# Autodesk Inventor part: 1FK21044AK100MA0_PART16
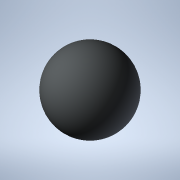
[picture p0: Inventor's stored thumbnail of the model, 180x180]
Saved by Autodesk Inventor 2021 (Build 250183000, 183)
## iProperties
Created: 2025-04
Part Number: 1FK21044AK100MA0_PART16
Material: Generic
Catalog Web Link: www.3dfindit.com
Description: -Servo synchronous motor
Document SubType Name: Modeling
Designer: psAdmin
Mass: 0.137258 g
Surface Area: 1.2868 cm^2
Volume: 0.137258 cm^3
Density: 1 g/cm^3
Appearance: PSOLRGB-212-217-219
Category: PARTsolutions
Title: 1FK21044AK100MA0_PART16
Author: Cadenas PARTsolutions
Comments: Servo synchronous motor
Sending System: PARTsolutions
Preprocessor: ST-DEVELOPER v19.3
PSOL_IDENT_0: {$CADENAS_DATA/23d-libs/siemens_ag/_cat_/5e/d8/1fk21044ak100ma0.prj},216 {VTYP=3D},{NB=1FK21044AK100
PSOL_IDENT_1: MA0_PART16},{LINA=1FK21044AK100MA0_PART16},{NN=1FK21044AK100MA0_PART16},{NOPRJ=TRUE},{DATE=19.08.202
PSOL_IDENT_2: 5 14:00:41},{GEOMDATE=30.07.2025 02:00:53},{VERSION=},{LINEID=10},{WBVAR=},{WBNUMERIC=}  {NB=1FK2104
PSOL_IDENT_3: 4AK100MA0_PART16},{LINA=1FK21044AK100MA0_PART16},{KT=DUMMY},{PREVIEW=../../../_pool_/cb/72/p_d211_xx
PSOL_IDENT_4: _00434j.png},{DESCSHORT=SIMOTICS S-1FK2 HD, SINAMICS S210 3AC 400V-480V, 0.95 Nm, 6000 rpm},{DESCLON
PSOL_IDENT_5: G=SIMOTICS S-1FK2 HD servo motor M0=1.27 Nm; PN = 0.6 kW at nN=6000 rpm (380-480 V); PN = 0.4 kW at
PSOL_IDENT_6: nN=3000 rpm (200-240 V); with holding brake; degree of protection IP64; cylindrical shaft D19x40mm;
PSOL_IDENT_7: absolute encoder 22-bit + 12-bit multiturn (encoder AM22DQC); with OCC interface; plug size M17, rot
PSOL_IDENT_8: atable; SIMOTICS S-1FK2 servomotorfor a wide range of uses in industrial environments. SIMOTICS S‑1F
PSOL_IDENT_9: K2 servomotors are compact synchronous motors with a high dynamic performance that set themselves ap
PSOL_IDENT_10: art as a result of their high power density, degree of protection and overload capability. The motor
PSOL_IDENT_11: s are available in two variants: as High Dynamic variant (highest dynamic performance as a result of
PSOL_IDENT_12: the low intrinsic moment of inertia for applications demanding a high dynamic performance with low
PSOL_IDENT_13: moved masses) - and as Compact variant (precise and stable closed-loop control for medium up to larg
PSOL_IDENT_14: e moved masses as a result of a medium intrinsic moment of inertia). SIMOTICSS‑1FK2 servomotors full
PSOL_IDENT_15: y exploit their strengths in a system with the SINAMICSS210 frequency converter and simple connectio
PSOL_IDENT_16: n using the one cable connection (OCC). Advantages include the short control and positioning times,
PSOL_IDENT_17: fast and precise correction of disturbing quantities as well as stable control with a high dynamic p
PSOL_IDENT_18: erformance. The servo motors can be configured to address a wide range of requirements. For example
PSOL_IDENT_19: with and without holding brake, IP64 or IP65 degree of protection, singleturn or multiturn absolute
PSOL_IDENT_20: encoders - to name just a few. Further, the servomotors are available in different shaft heights ext
PSOL_IDENT_21: ending from 20 to 100. A shaft sealing ring is available to achieve an IP65 degree of protection and
PSOL_IDENT_22: for subsequent mounting at the motor or as spare part. SIMOTICS - the optimum motor for each and ev
PSOL_IDENT_23: ery motion control application.},{INTNO=804766910005},{SUPPLIERALTNO=1FK2104-4AK10-0MA0},{MANUID=1FK
PSOL_IDENT_24: 21044AK100MA0},{MANUNAME=Siemens},{MANUTYPEDESC=Synchronous motor 1FK2-HD 1,27 Nm},{AAU732=SIMOTICS}
PSOL_IDENT_25: ,{AAO057=S-1FK2},{AAU734=SIMOTICS S-1FK2 HD servo motor M0=1.27 Nm; PN = 0.6 kW at nN=6000 rpm (380-
PSOL_IDENT_26: 480 V); PN = 0.4 kW at nN=3000 rpm (200-240 V); with holding brake; degree of protection IP64; cylin
PSOL_IDENT_27: drical shaft D19x40mm; absolute encoder 22-bit + 12-bit multiturn (encoder AM22DQC); with OCC interf
PSOL_IDENT_28: ace; plug size M17, rotatable;},{AAW338=Synchronous motor 1FK2-HD 1,27 Nm},{AAO742=SIMOTICS},{AAO663=
PSOL_IDENT_29: 4042948691076},{NOCUPEROU=1},{PRICEQUANTITY=1},{QUANTITYMIN=1},{QUANTITYINT=1},{CTN=85015100},{COO=D
PSOL_IDENT_30: E},{AAO676=1FK2104-4AK10-0MA0},{AAO677=Siemens AG},{ORDERUNIT=C62},{CONTENTUNIT=C62}
NB: 1FK21044AK100MA0_PART16
NT: Servo synchronous motor
NBSYN: $MANUID._PART16
LINA: 1FK21044AK100MA0_PART16
CATALOG: SIEMENS
PREVIEW: ../../../_pool_/cb/72/p_d211_xx_00434j.png
DESCSHORT: SIMOTICS S-1FK2 HD, SINAMICS S210 3AC 400V-480V, 0.95 Nm, 6000 rpm
DESCLONG: SIMOTICS S-1FK2 HD servo motor M0=1.27 Nm; PN = 0.6 kW at nN=6000 rpm (380-480 V); PN = 0.4 kW at nN=3000 rpm (200-240 V); with holding brake; degree of protect
INTNO: 804766910005
SUPPLIERALTNO: 1FK2104-4AK10-0MA0
MANUID: 1FK21044AK100MA0
MANUNAME: Siemens
MANUTYPEDESC: Synchronous motor 1FK2-HD 1,27 Nm
AAU732: SIMOTICS
AAO057: S-1FK2
AAU734: SIMOTICS S-1FK2 HD servo motor M0=1.27 Nm; PN = 0.6 kW at nN=6000 rpm (380-480 V); PN = 0.4 kW at nN=3000 rpm (200-240 V); with holding brake; degree of protect
AAW338: Synchronous motor 1FK2-HD 1,27 Nm
AAO742: SIMOTICS
AAO663: 4042948691076.0
NOCUPEROU: 1
PRICEQUANTITY: 1
QUANTITYMIN: 1
QUANTITYINT: 1
CTN: 85015100
COO: DE
ARTICLENO: 1FK21044AK100MA0_PART16
BOMINFO: 1FK21044AK100MA0_PART16
CREATOR: CADENAS GmbH
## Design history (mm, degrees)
feature "2025_04_17_15_35_41_0968"
body "Solid1"
